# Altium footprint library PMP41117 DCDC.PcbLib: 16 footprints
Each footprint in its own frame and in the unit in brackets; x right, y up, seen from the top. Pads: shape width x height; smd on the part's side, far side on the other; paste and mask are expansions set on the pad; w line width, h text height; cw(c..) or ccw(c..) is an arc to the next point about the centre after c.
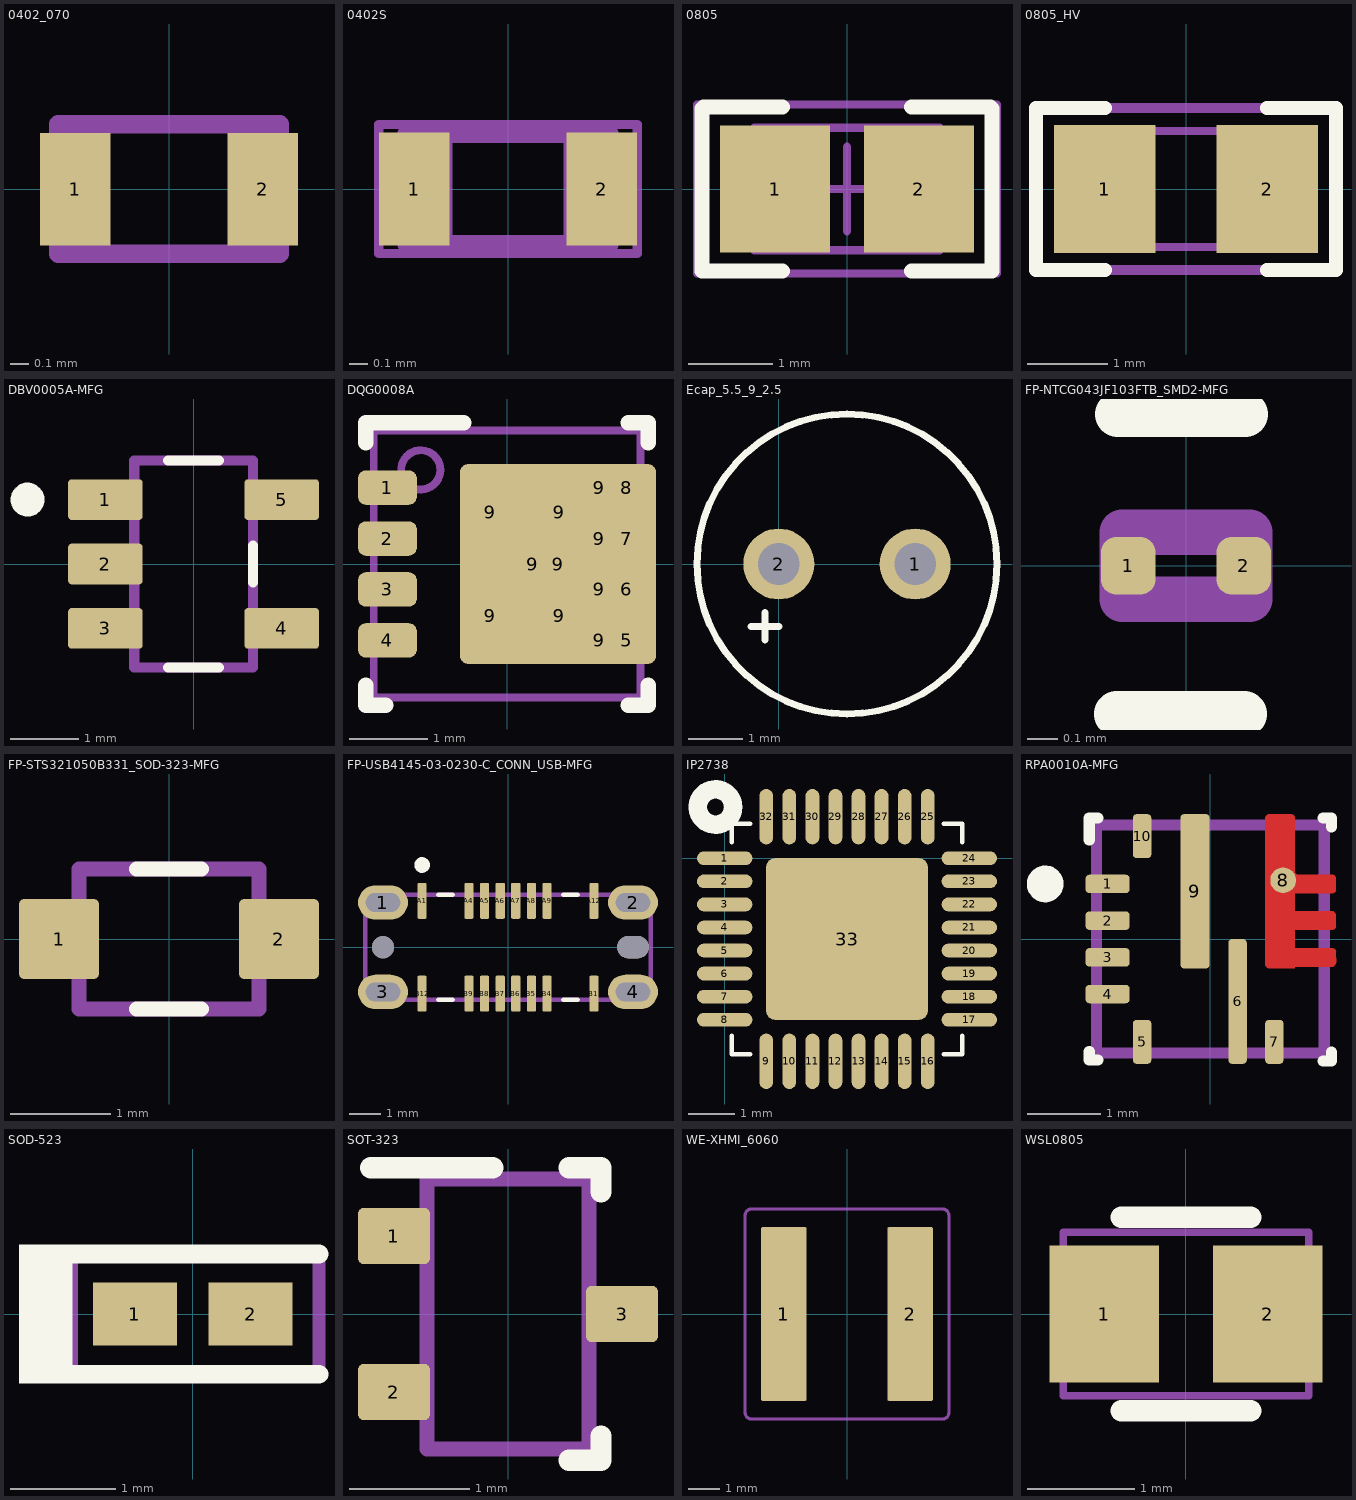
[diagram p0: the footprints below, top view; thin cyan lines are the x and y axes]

## 0402_070 [mil] "SMD, 2-Leads, Body 1.2x0.7mm, Height 0.7mm"
height 27.56
pads (2):
  rect 15x24 smd: 1(-20,0) 2(20,0)
Mechanical 5:
  lines w3.94: -23.62,-13.78 23.62,-13.78 23.62,13.78 -23.62,13.78 -23.62,-13.78
  text ".Designator" at -21.65,-5.91 h12
3D body: height 27.56, standoff 0, extent -13.78,-13.78 13.78,13.78
3D body: height 27.56, standoff 0, extent -23.62,-13.78 -13.78,13.78
3D body: height 27.56, standoff 0, extent 13.78,-13.78 23.62,13.78

## 0402S [mil] "Based on C0402S footprint from PADS legacy"
height 23.62
pads (2):
  rect 15x24 smd: 1(-20,0) 2(20,0)
Mechanical 5:
  lines w1.97: -27.56,-13.78 27.56,-13.78 27.56,13.78 -27.56,13.78 -27.56,-13.78
  text ".Designator" at -21.65,-5.91 h12
Mechanical 13:
  lines w3.94: -13.78,-11.81 -13.78,11.81 ; 13.78,-11.81 13.78,11.81 ; -21.65,-11.81 -21.65,11.81 21.65,11.81 21.65,-11.81 -21.65,-11.81
3D body: height 23.62, standoff 0, extent -21.63,-11.79 -13.8,11.79
3D body: height 23.62, standoff 0, extent -13.76,-11.79 13.76,11.79
3D body: height 23.62, standoff 0, extent 13.8,-11.79 21.63,11.79

## 0805 [mm] "0805 from SM-752 data"
height 1.45
pads (2):
  rect 1.3x1.5 smd: 1(-0.85,0) 2(0.85,0)
Top Overlay:
  lines w0.178: -0.762,-0.968 -1.717,-0.968 -1.717,0.95 -1.699,0.968 -0.762,0.968 ; 0.762,-0.968 1.717,-0.968 1.717,0.95 1.699,0.968 0.762,0.968
Mechanical 5:
  lines w0.1: -1.775,-1 -1.775,1 1.775,1 1.775,-1 -1.775,-1
  text ".Designator" at -1.525,-0.425 h0.81
Mechanical 13:
  lines w0.1: -0.65,-0.725 -0.65,0.725 ; 0.65,-0.725 0.65,0.725 ; -1.1,-0.725 -1.1,0.725 1.1,0.725 1.1,-0.725 -1.1,-0.725
Mechanical 15:
  lines w0.1: -0.5,0 0.5,0 ; 0,-0.5 0,0.5 ; -1.775,-1 -1.775,1 1.775,1 1.775,-1 -1.775,-1
3D body: height 1.45, standoff 0, extent 0.651,-0.724 1.099,0.724
3D body: height 1.45, standoff 0, extent -0.649,-0.724 0.649,0.724
3D body: height 1.45, standoff 0, extent -1.099,-0.724 -0.651,0.724

## 0805_HV [mil] "0805 with 30mil clearance between pads"
height 57.09
pads (2):
  rect 50x63 smd: 1(-40,0) 2(40,0)
Top Overlay:
  lines w7: -40,-40 -74,-40 -74,0 -74,40 -40,40 ; 40,-40 74,-40 74,0 74,40 40,40
Mechanical 5:
  lines w5: -74,-40 74,-40 74,40 -74,40 -74,-40
  text ".Designator" at -64,-17 h35
Mechanical 13:
  lines w3.94: -25.59,-28.54 -25.59,28.54 ; 25.59,-28.54 25.59,28.54 ; -43.31,-28.54 43.31,-28.54 43.31,28.54 -43.31,28.54 -43.31,-28.54
3D body: height 57.09, standoff 0, extent -43.29,-28.52 -25.61,28.52
3D body: height 57.09, standoff 0, extent -25.57,-28.52 25.57,28.52
3D body: height 57.09, standoff 0, extent 25.61,-28.52 43.29,28.52

## DBV0005A-MFG [mm]
height 1
pads (5):
  rrect17% 1.1x0.6 smd paste+0 mask+0: 1(-1.3,0.95) 2(-1.3,0) 3(-1.3,-0.95) 4(1.3,-0.95) 5(1.3,0.95)
Top Overlay:
  circle w0.25: c-2.45,0.95 r0.125
  lines w0.15: -0.375,-1.525 0.375,-1.525 ; -0.375,1.525 0.375,1.525 ; 0.875,-0.275 0.875,0.275
Mechanical 5:
  lines w0.15: -0.875,-1.525 -0.875,1.525 0.875,1.525 0.875,-1.525 -0.875,-1.525
  text ".Designator" at 0.05,0.217 h0.5
3D body "IC_TLV709A33DBVR_SOT23-5.STEP": height 1.45, standoff 0, extent -1.4,-1.45 1.4,1.45

## DQG0008A [mm] "SMD, 8-Leads, Body 3.3x3.3mm, Pitch 0.65mm"
height 1.1
pads (18):
  rrect45% 0.75x0.44 smd paste-0.05 mask-0.05: 1(-1.525,0.975) 2(-1.525,0.325) 3(-1.525,-0.325) 4(-1.525,-0.975) 5(1.525,-0.975) 6(1.525,-0.325) 7(1.525,0.325) 8(1.525,0.975)
  rrect50% 0.676x1.125 on Top Paste: 9(-0.212,-0.663) 9(-0.212,0.662) 9(0.664,-0.663) 9(0.664,0.662)
  rrect50% 1.775x2.45 on Top Solder: 9(0.327,0)
  rrect8% 2.5x2.55 smd paste-1.5 mask-1.5: 9(0.65,0)
  rrect50% 0.5x0.34 on Top Solder: 9(1.175,-0.975) 9(1.175,-0.325) 9(1.175,0.325) 9(1.175,0.975)
Top Overlay:
  lines w0.2: -1.8,-1.55 -1.8,-1.8 -1.55,-1.8 ; -1.8,1.55 -1.8,1.8 -0.55,1.8 ; 1.55,-1.8 1.8,-1.8 1.8,-1.55 ; 1.55,1.8 1.8,1.8 1.8,1.55
Mechanical 5:
  circle w0.1: c-1.1,1.2 r0.25
  lines w0.1: -1.7,-1.7 -1.7,1.7 1.7,1.7 1.7,-1.7 -1.7,-1.7
  text ".Designator" at -1.524,-0.508 h0.76
3D body "DQG0008A.stp": height 1.1, standoff 0, extent -1.65,-1.65 1.65,1.65

## Ecap_5.5_9_2.5 [mm]
height 1
pads (2):
  round 1.3 hole 0.762: 1(2.5,0) 2(0,0)
Top Overlay:
  circle w0.127: c1.25,0 r2.75
  lines w0.127: -0.508,-1.143 0,-1.143 ; -0.254,-1.397 -0.254,-0.889

## FP-NTCG043JF103FTB_SMD2-MFG [mm]
height 1
pads (2):
  rrect56% 0.18x0.19 smd paste+0 mask+0: 1(-0.19,0) 2(0.19,0)
Top Overlay:
  lines w0.15: -0.228,-0.488 0.192,-0.488 ; -0.225,0.5 0.195,0.5
Mechanical 5:
  lines w0.15: -0.21,-0.11 -0.21,0.11 0.21,0.11 0.21,-0.11 -0.21,-0.11
  text ".Designator" at 0.05,0.217 h0.5
3D body "Res_NTCG043JF103FTB_SMD2.STEP": height 0.22, standoff 0, extent -0.2,-0.1 0.2,0.1

## FP-STS321050B331_SOD-323-MFG [mm]
height 1
pads (2):
  rrect13% 0.8x0.8 smd paste+0 mask+0: 1(-1.1,0) 2(1.1,0)
Top Overlay:
  lines w0.15: -0.325,-0.7 0.325,-0.7 ; -0.325,0.7 0.325,0.7
Mechanical 5:
  lines w0.15: -0.9,-0.7 0.9,-0.7 0.9,0.7 -0.9,0.7 -0.9,-0.7
  text ".Designator" at 0.05,0.217 h0.5
3D body "Diode_STS321050B331_SOD-323.STEP": height 1, standoff 0, extent -1.397,-0.65 1.397,0.65

## FP-USB4145-03-0230-C_CONN_USB-MFG [mm]
height 1
pads (22):
  rrect100% 1.6x1.1 hole 0.6 slot 1.1 at 0 deg paste-1000 mask+0: 1(-4,1.43) 2(4,1.43) 3(-4,-1.43) 4(4,-1.43)
  rrect33% 0.3x1.15 smd paste+0 mask+0: A1(-2.75,1.485) A4(-1.25,1.485) A5(-0.75,1.485) A6(-0.25,1.485) A7(0.25,1.485) A8(0.75,1.485) A9(1.25,1.485) A12(2.75,1.485) B1(2.75,-1.485) B4(1.25,-1.485) B5(0.75,-1.485) B6(0.25,-1.485) B7(-0.25,-1.485) B8(-0.75,-1.485) B9(-1.25,-1.485) B12(-2.75,-1.485)
  round 0.71 hole 0.71 unplated paste-1000 mask+0: ""(-4,0)
  rrect100% 1.01x0.71 hole 0.71 slot 1.01 at 0 deg unplated paste-1000 mask+0: ""(4,0)
Top Overlay:
  circle w0.25: c-2.75,2.63 r0.125
  lines w0.15: -2.225,-1.68 -1.775,-1.68 ; -2.225,1.68 -1.775,1.68 ; 1.775,-1.68 2.225,-1.68 ; 1.775,1.68 2.225,1.68
Mechanical 5:
  lines w0.15: -4.57,-1.68 -4.57,1.68 4.57,1.68 4.57,-1.68 -4.57,-1.68
  text ".Designator" at 0,0 h0.5
3D body "Conn_USB4145-03-0230-C_CONN_USB.STEP": height 7.66, standoff -2.3, extent -4.475,-1.845 4.47,1.845

## IP2738 [mm]
height 1
pads (33):
  oval 1.2x0.3 smd: 1(0,0) 2(0,-0.5) 3(0,-1) 4(0,-1.5) 5(0,-2) 6(0,-2.5) 7(0,-3) 8(0,-3.5) 17(5.3,-3.5) 18(5.3,-3) 19(5.3,-2.5) 20(5.3,-2) 21(5.3,-1.5) 22(5.3,-1) 23(5.3,-0.5) 24(5.3,0)
  oval 0.3x1.2 smd: 9(0.9,-4.4) 10(1.4,-4.4) 11(1.9,-4.4) 12(2.4,-4.4) 13(2.9,-4.4) 14(3.4,-4.4) 15(3.9,-4.4) 16(4.4,-4.4) 25(4.4,0.9) 26(3.9,0.9) 27(3.4,0.9) 28(2.9,0.9) 29(2.4,0.9) 30(1.9,0.9) 31(1.4,0.9) 32(0.9,0.9)
  rrect10% 3.5x3.5 smd: 33(2.65,-1.75)
Top Overlay:
  circle w0.4: c-0.2,1.11 r0.382
  lines w0.1: 0.15,-3.85 0.15,-4.25 0.55,-4.25 ; 0.15,0.35 0.15,0.75 0.55,0.75 ; 4.75,-4.25 5.15,-4.25 5.15,-3.85 ; 4.75,0.75 5.15,0.75 5.15,0.35
Mechanical 5:
  text ".Designator" at -1.7,3 h1.02

## RPA0010A-MFG [mm]
height 1.1
pads (10):
  rrect40% 0.6x0.25 smd paste+0 mask+0: 1(-1.4,0.75) 2(-1.4,0.25) 3(-1.4,-0.25) 4(-1.4,-0.75)
  rrect40% 0.25x0.6 smd paste+0 mask+0: 5(-0.93,-1.4) 7(0.87,-1.4) 10(-0.93,1.4)
  rrect40% 0.25x1.7 smd paste-1000 mask+0: 6(0.37,-0.85)
  round 0.35 smd paste+0 mask+0: 8(0.99,0.8)
  rrect25% 0.4x2.1 smd paste-1000 mask+0: 9(-0.21,0.65)
Top Layer:
  region: 0.8,1.7 0.79,1.7 0.772,1.692 0.758,1.678 0.75,1.66 0.75,1.65 0.75,-0.35 0.75,-0.36 0.758,-0.378 0.772,-0.392 0.79,-0.4 0.8,-0.4 1.15,-0.4 1.15,-0.375 1.66,-0.375 1.67,-0.375 1.688,-0.367 1.702,-0.353 1.71,-0.335 1.71,-0.325 1.71,-0.175 1.71,-0.165 1.702,-0.147 1.688,-0.133 1.67,-0.125 1.66,-0.125 1.15,-0.125 1.15,0.125 1.66,0.125 1.67,0.125 1.688,0.133 1.702,0.147 1.71,0.165 1.71,0.175 1.71,0.325 1.71,0.335 1.702,0.353 1.688,0.367 1.67,0.375 1.66,0.375 1.15,0.375 1.15,0.625 1.66,0.625 1.67,0.625 1.688,0.633 1.702,0.647 1.71,0.665 1.71,0.675 1.71,0.825 1.71,0.835 1.702,0.853 1.688,0.867 1.67,0.875 1.66,0.875 1.2,0.875 1.19,0.876 1.172,0.883 1.158,0.897 1.151,0.915 1.15,0.925 1.15,1.65 1.15,1.66 1.142,1.678 1.128,1.692 1.11,1.7 1.1,1.7
Top Overlay:
  circle w0.25: c-2.25,0.75 r0.125
  lines w0.15: -1.65,-1.53 -1.65,-1.65 -1.53,-1.65 ; -1.65,1.35 -1.65,1.65 -1.53,1.65 ; 1.53,-1.66 1.65,-1.66 1.65,-1.54 ; 1.53,1.65 1.65,1.65 ; 1.65,1.525 1.65,1.645
Top Paste:
  drawing of 5 lines, arcs and shapes, not listed
Top Solder:
  region: 0.8,1.7 0.79,1.7 0.772,1.692 0.758,1.678 0.75,1.66 0.75,1.65 0.75,-0.35 0.75,-0.36 0.758,-0.378 0.772,-0.392 0.79,-0.4 0.8,-0.4 1.15,-0.4 1.15,-0.375 1.66,-0.375 1.67,-0.375 1.688,-0.367 1.702,-0.353 1.71,-0.335 1.71,-0.325 1.71,-0.175 1.71,-0.165 1.702,-0.147 1.688,-0.133 1.67,-0.125 1.66,-0.125 1.15,-0.125 1.15,0.125 1.66,0.125 1.67,0.125 1.688,0.133 1.702,0.147 1.71,0.165 1.71,0.175 1.71,0.325 1.71,0.335 1.702,0.353 1.688,0.367 1.67,0.375 1.66,0.375 1.15,0.375 1.15,0.625 1.66,0.625 1.67,0.625 1.688,0.633 1.702,0.647 1.71,0.665 1.71,0.675 1.71,0.825 1.71,0.835 1.702,0.853 1.688,0.867 1.67,0.875 1.66,0.875 1.2,0.875 1.19,0.876 1.172,0.883 1.158,0.897 1.151,0.915 1.15,0.925 1.15,1.65 1.15,1.66 1.142,1.678 1.128,1.692 1.11,1.7 1.1,1.7
Mechanical 5:
  lines w0.15: -1.55,-1.55 -1.55,1.55 1.55,1.55 1.55,-1.55 -1.55,-1.55
  text ".Designator" at 0.005,0 h0.5
3D body "IC_TPS56837RPAR_VQFN-HR10.STEP": height 1, standoff 0, extent -1.5,-1.5 1.5,1.5

## SOD-523 [mm] "NXP Semiconductor recommended land pattern, nominal STEP model"
height 0.7
pads (2):
  rect 0.8x0.6 smd paste-0.05: 1(-0.55,0) 2(0.55,0)
Top Overlay:
  rectangle: -1.653,-0.66 -1.145,0.661
  lines w0.178: -1.475,-0.572 0,-0.572 1.2,-0.572 ; -1.475,0.572 0,0.572 1.2,0.572
Mechanical 5:
  rectangle: -1.602,-0.635 -1.094,0.635
  lines w0.127: -1.475,-0.546 0,-0.546 1.2,-0.546 1.2,0.546 0,0.559 -1.475,0.559
  text ".Designator" at -0.991,-0.279 h0.56
3D body "SOD-523F.stp": height 0.72, standoff 0.02, extent -0.8,-0.399 0.8,0.399

## SOT-323 [mm] "Diodes Inc recommended land pattern.  2016-02-24"
height 1.1
pads (3):
  rrect21% 0.6x0.47 smd: 1(-0.95,0.65) 2(-0.95,-0.65) 3(0.95,0)
Top Overlay:
  lines w0.178: -1.143,1.219 -0.127,1.219 ; 0.508,-1.219 0.775,-1.219 0.775,-1.016 ; 0.508,1.219 0.775,1.219 0.775,1.016
Mechanical 5:
  lines w0.127: -1.125,-0.8 -1.125,-0.5 -0.975,-0.5 -0.935,-0.5 -0.884,-0.5 -0.725,-0.5 -0.675,-0.5 -0.675,-0.8 -0.725,-0.8 -0.884,-0.8 -0.935,-0.8 -0.975,-0.8 -1.125,-0.8 ; -1.125,0.5 -1.125,0.8 -0.975,0.8 -0.935,0.8 -0.884,0.8 -0.725,0.8 -0.675,0.8 -0.675,0.5 -0.725,0.5 -0.884,0.5 -0.935,0.5 -0.975,0.5 -1.125,0.5 ; -0.675,-1.125 -0.675,1.125 0.675,1.125 0.675,-1.125 -0.675,-1.125 ; 0.675,-0.15 0.725,-0.15 0.884,-0.15 0.935,-0.15 0.975,-0.15 1.125,-0.15 1.125,0.15 0.975,0.15 0.935,0.15 0.884,0.15 0.725,0.15 0.675,0.15 0.675,-0.15
  text ".Designator" at -0.25,0.9 h0.8
3D body "SC-70.stp": height 1.13, standoff 0.02, extent -1.125,-1.125 1.125,1.125

## WE-XHMI_6060 [mm] "SMD, 2-Leads, Body 6.65x6.45mm"
height 6.1
pads (2):
  rrect7% 1.45x5.5 smd: 1(-2,0) 2(2,0)
Mechanical 5:
  lines w0.1: -3.225,-3.125 ccw(c-3.025,-3.125) -3.025,-3.325 3.025,-3.325 ccw(c3.025,-3.125) 3.225,-3.125 3.225,3.125 ccw(c3.025,3.125) 3.025,3.325 -3.025,3.325 ccw(c-3.025,3.125) -3.225,3.125 -3.225,-3.125
  text ".Designator" at -2,-0.7 h1.85
3D body "WE-XHMI_6060.stp": height 5.78, standoff -0.02, extent -3.225,-3.325 3.225,3.325

## WSL0805 [mm] "Vishay"
height 0.59
pads (2):
  rect 1.02x1.27 smd: 1(-0.76,0) 2(0.76,0)
Top Overlay:
  lines w0.2: -0.6,-0.9 0.6,-0.9 ; -0.6,0.9 0.6,0.9
Mechanical 5:
  lines w0.07: -1.142,-0.762 -1.142,0.762 1.142,0.762 1.142,-0.762 -1.142,-0.762
  text ".Designator" at -1,-0.3 h0.55
3D body: height 0.59, standoff 0, extent -1.141,-0.761 -0.601,0.761
3D body: height 0.59, standoff 0, extent -0.599,-0.761 0.599,0.761
3D body: height 0.59, standoff 0, extent 0.601,-0.761 1.141,0.761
